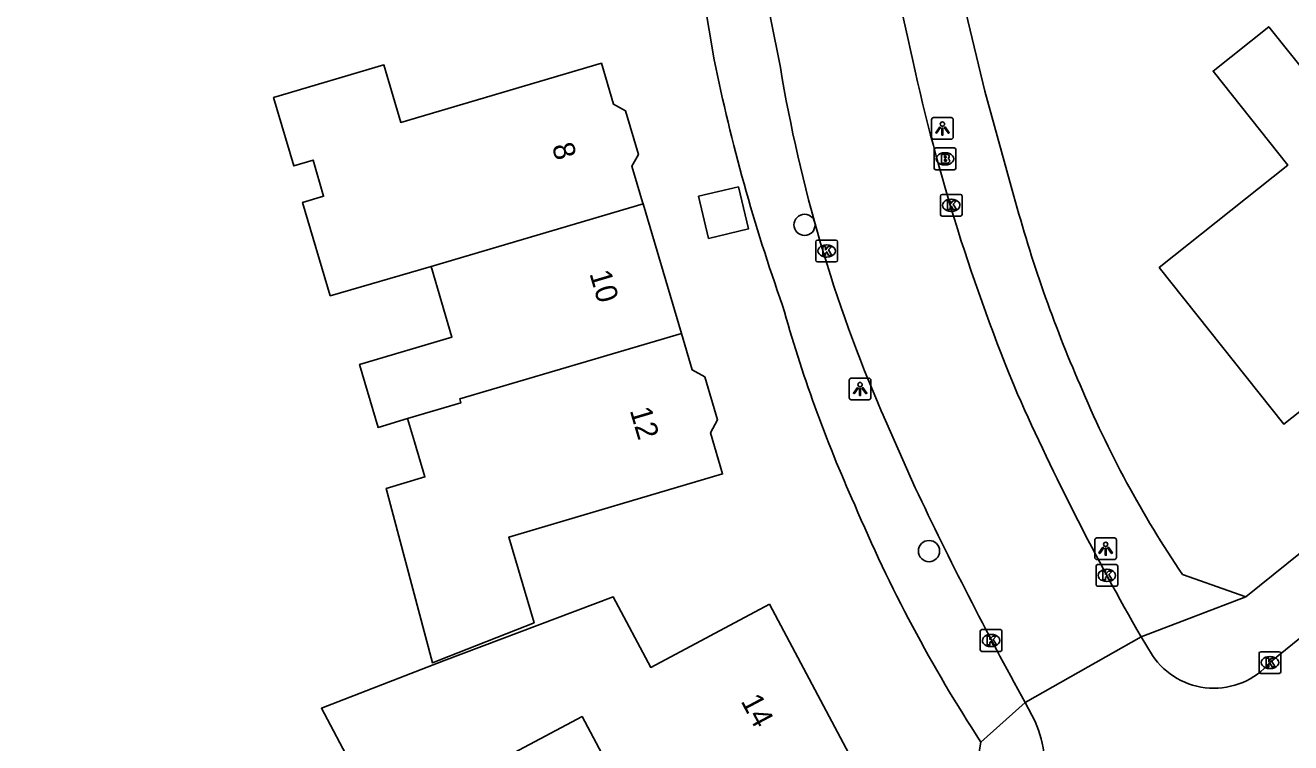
# Model space of a CAD drawing. Extents: x 161354 to 161876, y 382161 to 382804.
# Drawn here: x 161439.4 to 161497.7, y 382310.5 to 382343.6 of the extents above; entities that cross this region are included whole.
import ezdxf

# ---------------------------------------------------------------- set-up
doc = ezdxf.new("R2010")
doc.units = 0
for name, color, linetype in [('IMGEO_Boom', 7, 'Continuous'), ('IMGEO_Brandkraan', 7, 'Continuous'), ('IMGEO_Kolk', 7, 'Continuous'), ('IMGEO_Lichtpunt', 7, 'Continuous'), ('IMGEO_Pand', 7, 'Continuous'), ('IMGEO_Pand_nummerreeks', 7, 'Continuous'), ('IMGEO_Rijbaan_lokaal_open', 7, 'Continuous'), ('IMGEO_Voetpad_open', 7, 'Continuous')]:
    doc.layers.add(name, color=color, linetype=linetype)

msp = doc.modelspace()

# ---------------------------------------------------------------- linework, layer by layer
at = {"layer": 'IMGEO_Boom'}
for centre in [(161475.339, 382334.391), (161481.076, 382319.369)]:
    msp.add_circle(centre, 0.489, dxfattribs=at)
at = {"layer": 'IMGEO_Brandkraan'}
for p, q in [((161481.31, 382337.004), (161481.31, 382337.856)), ((161481.385, 382337.93), (161482.237, 382337.93)), ((161481.798, 382337.71), (161481.823, 382337.71)), ((161482.311, 382337.856), (161482.311, 382337.004)), ((161481.821, 382337.15), (161481.796, 382337.15)), ((161482.237, 382336.93), (161481.385, 382336.93))]:
    msp.add_line(p, q, dxfattribs=at)
for points in [[(161481.31, 382337.004), (161481.31, 382337.856)], [(161481.385, 382337.93), (161482.237, 382337.93)], [(161482.311, 382337.856), (161482.311, 382337.004)], [(161481.658, 382337.63), (161481.658, 382337.23), (161481.871, 382337.23)], [(161481.889, 382337.63), (161481.658, 382337.63)], [(161481.837, 382337.549), (161481.783, 382337.549), (161481.783, 382337.473)], [(161481.783, 382337.473), (161481.836, 382337.473)], [(161481.845, 382337.397), (161481.783, 382337.397), (161481.783, 382337.316)], [(161481.783, 382337.316), (161481.845, 382337.316)], [(161482.237, 382336.93), (161481.385, 382336.93)]]:
    msp.add_lwpolyline(points, dxfattribs=at)
for centre, radius, start, end in [((161481.387, 382337.854), 0.0765, 91.55205, 178.44795), ((161481.387, 382337.854), 0.0765, 91.55205, 178.44795), ((161482.235, 382337.854), 0.0765, 1.55205, 88.44795), ((161482.235, 382337.854), 0.0765, 1.55205, 88.44795), ((161481.838, 382337.511), 0.0379, 267.82845, 90.93552), ((161481.846, 382337.356), 0.0404, 269.87594, 90.50774), ((161481.877, 382337.481), 0.251, 268.66757, 293.53466), ((161481.893, 382337.485), 0.145, 59.4692, 91.53667), ((161481.918, 382337.532), 0.0922, 285.51372, 58.15012), ((161481.923, 382337.34), 0.105, 301.31148, 78.98903), ((161481.387, 382337.006), 0.0765, 181.55205, 268.44795), ((161481.387, 382337.006), 0.0765, 181.55205, 268.44795), ((161482.235, 382337.006), 0.0765, 271.55205, 358.44795), ((161482.235, 382337.006), 0.0765, 271.55205, 358.44795)]:
    msp.add_arc(centre, radius, start, end, dxfattribs=at)
for centre, major_axis, ratio, start_param, end_param in [((161481.797, 382337.43), (-0.387, 0.002), 0.722429, 4.712389, 7.853982), ((161481.822, 382337.43), (-0.39, 0.002), 0.717154, 1.570796, 4.712389)]:
    msp.add_ellipse(centre, major_axis=major_axis, ratio=ratio, start_param=start_param, end_param=end_param, dxfattribs=at)
at = {"layer": 'IMGEO_Kolk'}
for p, q in [((161481.599, 382334.866), (161481.599, 382335.718)), ((161481.674, 382335.792), (161482.526, 382335.792)), ((161482.087, 382335.572), (161482.112, 382335.572)), ((161482.6, 382335.718), (161482.6, 382334.866)), ((161482.526, 382334.792), (161481.674, 382334.792)), ((161482.11, 382335.012), (161482.085, 382335.012)), ((161475.857, 382332.761), (161475.857, 382333.613)), ((161475.932, 382333.687), (161476.784, 382333.687)), ((161476.858, 382333.613), (161476.858, 382332.761)), ((161476.345, 382333.467), (161476.37, 382333.467)), ((161476.784, 382332.687), (161475.932, 382332.687)), ((161476.368, 382332.907), (161476.343, 382332.907)), ((161488.771, 382317.823), (161488.771, 382318.675)), ((161488.846, 382318.749), (161489.698, 382318.749)), ((161489.259, 382318.529), (161489.284, 382318.529)), ((161489.772, 382318.675), (161489.772, 382317.823)), ((161489.282, 382317.969), (161489.257, 382317.969)), ((161489.698, 382317.749), (161488.846, 382317.749)), ((161483.435, 382314.825), (161483.435, 382315.677)), ((161483.51, 382315.751), (161484.362, 382315.751)), ((161483.923, 382315.531), (161483.948, 382315.531)), ((161484.436, 382315.677), (161484.436, 382314.825)), ((161483.946, 382314.971), (161483.921, 382314.971)), ((161484.362, 382314.751), (161483.51, 382314.751)), ((161496.289, 382313.809), (161496.289, 382314.661)), ((161496.364, 382314.735), (161497.216, 382314.735)), ((161496.777, 382314.515), (161496.802, 382314.515)), ((161497.29, 382314.661), (161497.29, 382313.809)), ((161496.8, 382313.955), (161496.775, 382313.955)), ((161497.216, 382313.735), (161496.364, 382313.735))]:
    msp.add_line(p, q, dxfattribs=at)
for points in [[(161481.599, 382334.866), (161481.599, 382335.718)], [(161481.674, 382335.792), (161482.526, 382335.792)], [(161481.92, 382335.492), (161482.043, 382335.492), (161482.043, 382335.341), (161482.173, 382335.492), (161482.337, 382335.492), (161482.191, 382335.341), (161482.344, 382335.092), (161482.192, 382335.092), (161482.107, 382335.256), (161482.043, 382335.189), (161482.043, 382335.092), (161481.92, 382335.092), (161481.92, 382335.492)], [(161482.6, 382335.718), (161482.6, 382334.866)], [(161482.526, 382334.792), (161481.674, 382334.792)], [(161475.857, 382332.761), (161475.857, 382333.613)], [(161475.932, 382333.687), (161476.784, 382333.687)], [(161476.858, 382333.613), (161476.858, 382332.761)], [(161476.178, 382333.387), (161476.301, 382333.387), (161476.301, 382333.236), (161476.431, 382333.387), (161476.595, 382333.387), (161476.449, 382333.236), (161476.602, 382332.987), (161476.45, 382332.987), (161476.365, 382333.151), (161476.301, 382333.084), (161476.301, 382332.987), (161476.178, 382332.987), (161476.178, 382333.387)], [(161476.784, 382332.687), (161475.932, 382332.687)], [(161488.771, 382317.823), (161488.771, 382318.675)], [(161488.846, 382318.749), (161489.698, 382318.749)], [(161489.092, 382318.449), (161489.215, 382318.449), (161489.215, 382318.298), (161489.345, 382318.449), (161489.509, 382318.449), (161489.363, 382318.298), (161489.516, 382318.049), (161489.364, 382318.049), (161489.279, 382318.213), (161489.215, 382318.146), (161489.215, 382318.049), (161489.092, 382318.049), (161489.092, 382318.449)], [(161489.772, 382318.675), (161489.772, 382317.823)], [(161489.698, 382317.749), (161488.846, 382317.749)], [(161483.435, 382314.825), (161483.435, 382315.677)], [(161483.51, 382315.751), (161484.362, 382315.751)], [(161484.436, 382315.677), (161484.436, 382314.825)], [(161483.756, 382315.451), (161483.879, 382315.451), (161483.879, 382315.3), (161484.009, 382315.451), (161484.173, 382315.451), (161484.027, 382315.3), (161484.18, 382315.051), (161484.028, 382315.051), (161483.943, 382315.215), (161483.879, 382315.148), (161483.879, 382315.051), (161483.756, 382315.051), (161483.756, 382315.451)], [(161484.362, 382314.751), (161483.51, 382314.751)], [(161496.289, 382313.809), (161496.289, 382314.661)], [(161496.364, 382314.735), (161497.216, 382314.735)], [(161496.61, 382314.435), (161496.733, 382314.435), (161496.733, 382314.284), (161496.863, 382314.435), (161497.027, 382314.435), (161496.881, 382314.284), (161497.034, 382314.035), (161496.882, 382314.035), (161496.797, 382314.199), (161496.733, 382314.132), (161496.733, 382314.035), (161496.61, 382314.035), (161496.61, 382314.435)], [(161497.29, 382314.661), (161497.29, 382313.809)], [(161497.216, 382313.735), (161496.364, 382313.735)]]:
    msp.add_lwpolyline(points, dxfattribs=at)
for centre, start, end in [((161481.676, 382335.716), 91.55205, 178.44795), ((161481.676, 382335.716), 91.55205, 178.44795), ((161482.524, 382335.716), 1.55205, 88.44795), ((161482.524, 382335.716), 1.55205, 88.44795), ((161481.676, 382334.868), 181.55205, 268.44795), ((161481.676, 382334.868), 181.55205, 268.44795), ((161482.524, 382334.868), 271.55205, 358.44795), ((161482.524, 382334.868), 271.55205, 358.44795), ((161475.934, 382333.611), 91.55205, 178.44795), ((161475.934, 382333.611), 91.55205, 178.44795), ((161476.782, 382333.611), 1.55205, 88.44795), ((161476.782, 382333.611), 1.55205, 88.44795), ((161475.934, 382332.763), 181.55205, 268.44795), ((161475.934, 382332.763), 181.55205, 268.44795), ((161476.782, 382332.763), 271.55205, 358.44795), ((161476.782, 382332.763), 271.55205, 358.44795), ((161488.848, 382318.673), 91.55205, 178.44795), ((161488.848, 382318.673), 91.55205, 178.44795), ((161489.696, 382318.673), 1.55205, 88.44795), ((161489.696, 382318.673), 1.55205, 88.44795), ((161488.848, 382317.825), 181.55205, 268.44795), ((161488.848, 382317.825), 181.55205, 268.44795), ((161489.696, 382317.825), 271.55205, 358.44795), ((161489.696, 382317.825), 271.55205, 358.44795), ((161483.512, 382315.675), 91.55205, 178.44795), ((161483.512, 382315.675), 91.55205, 178.44795), ((161484.36, 382315.675), 1.55205, 88.44795), ((161484.36, 382315.675), 1.55205, 88.44795), ((161483.512, 382314.827), 181.55205, 268.44795), ((161483.512, 382314.827), 181.55205, 268.44795), ((161484.36, 382314.827), 271.55205, 358.44795), ((161484.36, 382314.827), 271.55205, 358.44795), ((161496.366, 382314.659), 91.55205, 178.44795), ((161496.366, 382314.659), 91.55205, 178.44795), ((161497.214, 382314.659), 1.55205, 88.44795), ((161497.214, 382314.659), 1.55205, 88.44795), ((161496.366, 382313.811), 181.55205, 268.44795), ((161496.366, 382313.811), 181.55205, 268.44795), ((161497.214, 382313.811), 271.55205, 358.44795), ((161497.214, 382313.811), 271.55205, 358.44795)]:
    msp.add_arc(centre, 0.0765, start, end, dxfattribs=at)
for centre, major_axis, ratio, start_param, end_param in [((161482.086, 382335.292), (-0.387, 0.002), 0.722429, 4.712389, 7.853982), ((161482.111, 382335.292), (-0.39, 0.002), 0.717154, 1.570796, 4.712389), ((161476.344, 382333.187), (-0.387, 0.002), 0.722429, 4.712389, 7.853982), ((161476.369, 382333.187), (-0.39, 0.002), 0.717154, 1.570796, 4.712389), ((161489.258, 382318.249), (-0.387, 0.002), 0.722429, 4.712389, 7.853982), ((161489.283, 382318.249), (-0.39, 0.002), 0.717154, 1.570796, 4.712389), ((161483.922, 382315.251), (-0.387, 0.002), 0.722429, 4.712389, 7.853982), ((161483.947, 382315.251), (-0.39, 0.002), 0.717154, 1.570796, 4.712389), ((161496.776, 382314.235), (-0.387, 0.002), 0.722429, 4.712389, 7.853982), ((161496.801, 382314.235), (-0.39, 0.002), 0.717154, 1.570796, 4.712389)]:
    msp.add_ellipse(centre, major_axis=major_axis, ratio=ratio, start_param=start_param, end_param=end_param, dxfattribs=at)
at = {"layer": 'IMGEO_Lichtpunt'}
for p, q in [((161481.195, 382339.234), (161481.195, 382338.427)), ((161481.195, 382339.234), (161481.195, 382338.427)), ((161482.097, 382339.329), (161481.289, 382339.329)), ((161482.097, 382339.329), (161481.289, 382339.329)), ((161482.191, 382338.427), (161482.191, 382339.234)), ((161482.191, 382338.427), (161482.191, 382339.234)), ((161481.289, 382338.333), (161482.097, 382338.333)), ((161481.289, 382338.333), (161482.097, 382338.333)), ((161477.401, 382327.239), (161477.401, 382326.432)), ((161477.401, 382327.239), (161477.401, 382326.432)), ((161478.303, 382327.334), (161477.495, 382327.334)), ((161478.303, 382327.334), (161477.495, 382327.334)), ((161478.397, 382326.432), (161478.397, 382327.239)), ((161478.397, 382326.432), (161478.397, 382327.239)), ((161477.495, 382326.338), (161478.303, 382326.338)), ((161477.495, 382326.338), (161478.303, 382326.338)), ((161488.717, 382319.882), (161488.717, 382319.075)), ((161488.717, 382319.882), (161488.717, 382319.075)), ((161489.619, 382319.977), (161488.811, 382319.977)), ((161489.619, 382319.977), (161488.811, 382319.977)), ((161489.713, 382319.075), (161489.713, 382319.882)), ((161489.713, 382319.075), (161489.713, 382319.882)), ((161488.811, 382318.981), (161489.619, 382318.981)), ((161488.811, 382318.981), (161489.619, 382318.981))]:
    msp.add_line(p, q, dxfattribs=at)
for points in [[(161481.569, 382338.898), (161481.608, 382338.87), (161481.42, 382338.608), (161481.382, 382338.635), (161481.569, 382338.898)], [(161481.671, 382338.85), (161481.718, 382338.85), (161481.718, 382338.528), (161481.671, 382338.528), (161481.671, 382338.85)], [(161481.781, 382338.87), (161481.819, 382338.897), (161482.006, 382338.635), (161481.967, 382338.607), (161481.781, 382338.87)], [(161477.775, 382326.903), (161477.814, 382326.875), (161477.626, 382326.613), (161477.588, 382326.64), (161477.775, 382326.903)], [(161477.877, 382326.855), (161477.924, 382326.855), (161477.924, 382326.533), (161477.877, 382326.533), (161477.877, 382326.855)], [(161477.987, 382326.875), (161478.025, 382326.902), (161478.212, 382326.64), (161478.173, 382326.612), (161477.987, 382326.875)], [(161489.091, 382319.546), (161489.13, 382319.518), (161488.942, 382319.256), (161488.904, 382319.283), (161489.091, 382319.546)], [(161489.193, 382319.498), (161489.24, 382319.498), (161489.24, 382319.176), (161489.193, 382319.176), (161489.193, 382319.498)], [(161489.303, 382319.518), (161489.341, 382319.545), (161489.528, 382319.283), (161489.489, 382319.255), (161489.303, 382319.518)]]:
    msp.add_lwpolyline(points, dxfattribs=at)
for centre in [(161481.694, 382339.032), (161477.9, 382327.037), (161489.216, 382319.68)]:
    msp.add_circle(centre, 0.0994, dxfattribs=at)
for centre, start, end in [((161481.289, 382339.234), 90, 180), ((161481.289, 382339.234), 90, 180), ((161482.097, 382339.234), 0, 90), ((161482.097, 382339.234), 0, 90), ((161481.289, 382338.427), 180, 270), ((161481.289, 382338.427), 180, 270), ((161482.097, 382338.427), 270, 0), ((161482.097, 382338.427), 270, 360), ((161477.495, 382327.239), 90, 180), ((161477.495, 382327.239), 90, 180), ((161478.303, 382327.239), 0, 90), ((161478.303, 382327.239), 0, 90), ((161477.495, 382326.432), 180, 270), ((161477.495, 382326.432), 180, 270), ((161478.303, 382326.432), 270, 0), ((161478.303, 382326.432), 270, 360), ((161488.811, 382319.882), 90, 180), ((161488.811, 382319.882), 90, 180), ((161489.619, 382319.882), 0, 90), ((161489.619, 382319.882), 0, 90), ((161488.811, 382319.075), 180, 270), ((161488.811, 382319.075), 180, 270), ((161489.619, 382319.075), 270, 0), ((161489.619, 382319.075), 270, 360)]:
    msp.add_arc(centre, 0.0946, start, end, dxfattribs=at)
at = {"layer": 'IMGEO_Pand'}
for points in [[(161505.918, 382332.008), (161502.662, 382329.412), (161502.518, 382328.135), (161501.894, 382327.638), (161500.663, 382327.777), (161500, 382327.253), (161497.42, 382325.215), (161491.686, 382332.42), (161497.616, 382337.139), (161494.169, 382341.47), (161496.735, 382343.512), (161498.649, 382341.115)], [(161458.129, 382332.474), (161453.48, 382331.124), (161452.21, 382335.424), (161453.179, 382335.71), (161452.689, 382337.37), (161451.801, 382337.108), (161450.872, 382340.252), (161455.952, 382341.755), (161456.734, 382339.105), (161465.979, 382341.834), (161466.537, 382339.945), (161467.086, 382339.646), (161467.68, 382337.634), (161467.382, 382337.086), (161467.868, 382335.442), (161467.896, 382335.364)], [(161472.289, 382336.141), (161472.751, 382334.201), (161470.916, 382333.764), (161470.454, 382335.705), (161472.289, 382336.141)], [(161458.129, 382332.474), (161467.896, 382335.364)], [(161467.896, 382335.364), (161469.662, 382329.389)], [(161457.05, 382325.47), (161455.689, 382325.067), (161454.833, 382327.966), (161459.09, 382329.223), (161458.129, 382332.474)], [(161469.662, 382329.389), (161470.156, 382327.712), (161470.747, 382327.391), (161471.332, 382325.408), (161471.006, 382324.807), (161471.563, 382322.92), (161461.712, 382320.009), (161462.877, 382316.067), (161458.504, 382314.347), (161458.192, 382314.224), (161456.058, 382322.257), (161457.844, 382322.784), (161457.364, 382324.406), (161457.139, 382325.168), (161457.05, 382325.47)], [(161469.662, 382329.389), (161459.45, 382326.375), (161459.503, 382326.197), (161457.05, 382325.47)], [(161473.729, 382316.918), (161477.514, 382309.794), (161477.004, 382309.524), (161477.33, 382308.911), (161474.644, 382307.484), (161474.333, 382308.07), (161469.531, 382305.518), (161468.703, 382307.077), (161467.82, 382306.608), (161465.09, 382311.746), (161455.881, 382306.854), (161453.078, 382312.13), (161458.706, 382314.316), (161466.527, 382317.259), (161468.254, 382314.009), (161473.729, 382316.918)]]:
    msp.add_lwpolyline(points, dxfattribs=at)
at = {"layer": 'IMGEO_Rijbaan_lokaal_open'}
for points in [[(161472.846, 382349.505), (161473.315, 382346.221), (161474.229, 382341.636)], [(161478.903, 382325.758), (161480.444, 382322.283)], [(161502.8, 382319.05), (161500, 382316.808), (161498.551, 382315.66), (161496.788, 382314.232)], [(161485.505, 382312.399), (161490.849, 382315.425)], [(161491.37, 382314.562), (161490.849, 382315.425)], [(161485.505, 382312.399), (161485.969, 382311.517)]]:
    msp.add_lwpolyline(points, dxfattribs=at)
for centre, radius, start, end in [((161550.911, 382358.887), 72.581, 187.26923, 193.48629), ((161567.752, 382360.955), 89.46, 192.25868, 202.58858), ((161540.887, 382352.631), 67.559, 189.36653, 203.43912), ((161596.458, 382376.32), 121.907, 204.07382, 209.96796), ((161642.711, 382399.132), 179.545, 205.34217, 208.88632), ((161494.206, 382316.476), 3.421, 214.01295, 319.01611), ((161480.946, 382309.36), 5.466, 348.04656, 23.24008)]:
    msp.add_arc(centre, radius, start, end, dxfattribs=at)
at = {"layer": 'IMGEO_Voetpad_open'}
for points in [[(161617.144, 382396.335), (161578.374, 382372.283), (161567.929, 382365.979), (161532.97, 382344.41), (161519.365, 382335.787), (161506.91, 382326.302), (161500, 382320.746), (161495.67, 382317.265)], [(161471.178, 382341.99), (161470.024, 382348.841)], [(161482.485, 382345.416), (161483.643, 382340.539), (161484.991, 382335.711)], [(161492.761, 382318.284), (161495.67, 382317.265)], [(161495.67, 382317.265), (161490.849, 382315.425)], [(161485.505, 382312.399), (161483.463, 382310.577)], [(161430.356, 382262.72), (161462.576, 382290.867), (161473.855, 382299.824), (161482.817, 382306.734), (161483.463, 382310.577)]]:
    msp.add_lwpolyline(points, dxfattribs=at)
for centre, radius, start, end in [((161552.785, 382358.627), 83.286, 191.52291, 199.60785), ((161545.113, 382351.906), 62.265, 195.07589, 203.55705), ((161535.537, 382347.65), 63.517, 195.49792, 204.30672), ((161533.852, 382346.147), 49.647, 202.65877, 214.14043), ((161541.197, 382348.298), 68.964, 202.86139, 213.15888)]:
    msp.add_arc(centre, radius, start, end, dxfattribs=at)

# ---------------------------------------------------------------- texts
at = {"layer": 'IMGEO_Pand_nummerreeks'}
for s, rotation, p in [('8', 286.44941, (161463.686, 382338.014)), ('10', 286.44941, (161465.418, 382332.152)), ('12', 286.44941, (161467.277, 382325.852)), ('14', 297.98305, (161472.38, 382312.466))]:
    msp.add_text(s, height=1, rotation=rotation, dxfattribs=at).set_placement(p)

doc.saveas('drawing.dxf')
